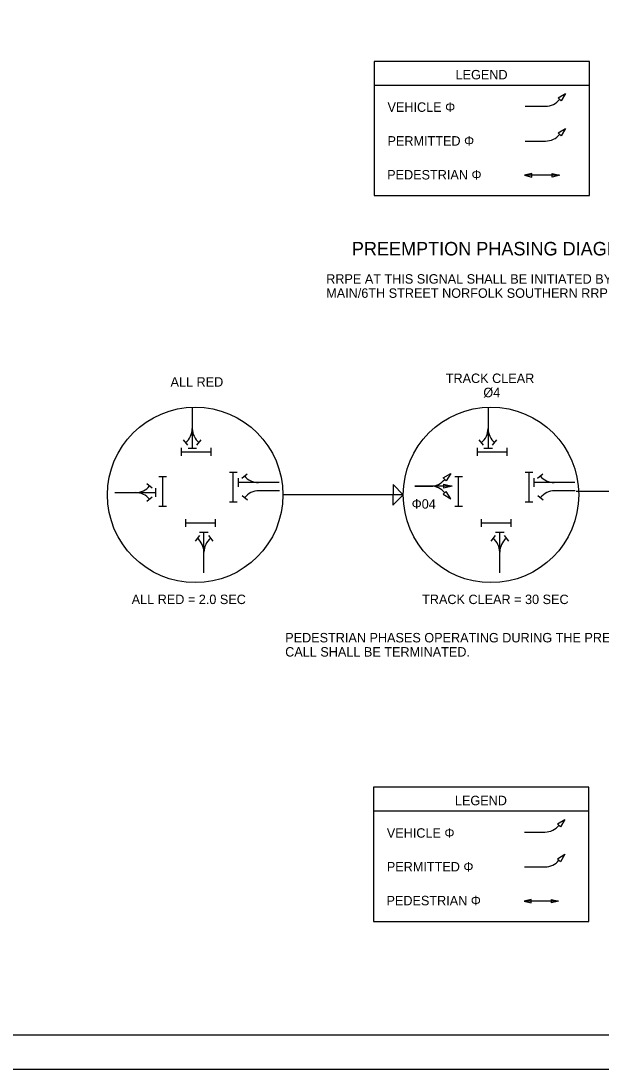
# Model space of a CAD drawing. Extents: x 0 to 680, y 0 to 551.
# Drawn here: x 337.3 to 509.1, y 0 to 310.4 of the extents above; entities that cross this region are included whole.
import ezdxf

# ---------------------------------------------------------------- set-up
doc = ezdxf.new("R2010")
doc.units = 0
for name, color, linetype in [('SG_P_Text', 7, 'Continuous'), ('SH_Border', 7, 'Continuous'), ('SH_Cut_Line', 7, 'Continuous'), ('SH_Data', 7, 'Continuous'), ('SH_Text', 7, 'Continuous')]:
    doc.layers.add(name, color=color, linetype=linetype)

msp = doc.modelspace()

# ---------------------------------------------------------------- linework, layer by layer
at = {"layer": 'SG_P_Text'}
for p, q in [((441.87, 291.42), (505.68, 291.42)), ((486.59, 285.15), (492.7, 285.15)), ((486.59, 274.82), (492.7, 274.82)), ((496.76, 264.68), (486.49, 264.68)), ((388.06, 195.78), (388.06, 189.67)), ((388.06, 195.78), (388.06, 189.67)), ((388.06, 195.78), (388.06, 183.77)), ((475.66, 195.78), (475.66, 189.67)), ((475.66, 195.78), (475.66, 189.67)), ((475.66, 195.78), (475.66, 183.77)), ((386.72, 184.74), (385.44, 186.33)), ((389.39, 184.74), (390.68, 186.33)), ((474.32, 184.74), (473.04, 186.33)), ((477, 184.74), (478.28, 186.33)), ((384.8, 183.93), (384.8, 181.65)), ((389.32, 183.77), (386.79, 183.77)), ((393.57, 183.93), (393.57, 181.65)), ((472.4, 183.93), (472.4, 181.65)), ((476.93, 183.77), (474.39, 183.77)), ((481.18, 183.93), (481.18, 181.65)), ((384.8, 182.79), (393.57, 182.79)), ((472.4, 182.79), (481.18, 182.79)), ((380.46, 175.42), (378.18, 175.42)), ((379.32, 166.64), (379.32, 175.42)), ((401.32, 176.65), (399.04, 176.65)), ((400.18, 167.88), (400.18, 176.65)), ((401.74, 172.42), (401.74, 174.95)), ((402.71, 175.03), (404.3, 176.31)), ((468.07, 175.42), (465.79, 175.42)), ((466.93, 166.64), (466.93, 175.42)), ((488.92, 176.65), (486.64, 176.65)), ((487.78, 167.88), (487.78, 176.65)), ((489.34, 172.42), (489.34, 174.95)), ((490.32, 175.03), (491.91, 176.31)), ((376.2, 172.05), (374.6, 173.33)), ((377.17, 171.98), (377.17, 169.44)), ((413.75, 173.69), (401.74, 173.69)), ((413.75, 173.69), (407.64, 173.69)), ((413.84, 171.23), (407.73, 171.23)), ((454.01, 172.63), (458.67, 172.63)), ((465.02, 172.63), (454.01, 172.63)), ((454.01, 172.63), (458.67, 172.63)), ((501.35, 173.69), (489.34, 173.69)), ((501.35, 173.69), (495.24, 173.69)), ((501.45, 171.23), (495.34, 171.23)), ((365.16, 170.71), (377.17, 170.71)), ((365.16, 170.71), (371.27, 170.71)), ((365.16, 170.71), (371.27, 170.71)), ((376.2, 169.37), (374.6, 168.09)), ((401.32, 167.88), (399.04, 167.88)), ((402.81, 169.89), (404.4, 168.61)), ((488.92, 167.88), (486.64, 167.88)), ((490.41, 169.89), (492, 168.61)), ((380.46, 166.64), (378.18, 166.64)), ((468.07, 166.64), (465.79, 166.64)), ((386.01, 162.86), (386.01, 160.58)), ((386.01, 161.72), (394.78, 161.72)), ((394.78, 162.86), (394.78, 160.58)), ((473.61, 162.86), (473.61, 160.58)), ((473.61, 161.72), (482.39, 161.72)), ((482.39, 162.86), (482.39, 160.58)), ((390.23, 158.95), (392.77, 158.95)), ((391.5, 146.94), (391.5, 158.95)), ((477.84, 158.95), (480.38, 158.95)), ((479.11, 146.94), (479.11, 158.95)), ((390.16, 157.98), (388.88, 156.38)), ((392.84, 157.98), (394.12, 156.38)), ((477.77, 157.98), (476.49, 156.38)), ((480.45, 157.98), (481.73, 156.38)), ((391.5, 146.94), (391.5, 153.05)), ((391.5, 146.94), (391.5, 153.05)), ((479.11, 146.94), (479.11, 153.05)), ((479.11, 146.94), (479.11, 153.05)), ((441.68, 76.46), (505.49, 76.46)), ((486.4, 70.19), (492.51, 70.19)), ((486.4, 59.85), (492.51, 59.85)), ((496.56, 49.71), (486.3, 49.71))]:
    msp.add_line(p, q, dxfattribs=at)
for points in [[(505.68, 298.42), (441.91, 298.42), (441.91, 258.67), (505.68, 258.67)], [(496.39, 287.58), (498.6, 288.9), (497.27, 286.69)], [(496.39, 277.24), (498.6, 278.56), (497.27, 276.35)], [(488.58, 265.2), (486.49, 264.68), (488.58, 264.16)], [(494.67, 265.2), (496.76, 264.68), (494.67, 264.16)], [(462.36, 175.05), (464.58, 176.37), (463.25, 174.16)], [(462.36, 170.21), (464.58, 168.88), (463.25, 171.09)], [(462.52, 173.25), (465.02, 172.63), (462.52, 172)], [(505.49, 83.46), (441.72, 83.46), (441.72, 43.71), (505.49, 43.71)], [(496.2, 72.61), (498.41, 73.94), (497.08, 71.73)], [(496.2, 62.27), (498.41, 63.6), (497.08, 61.39)], [(488.38, 50.23), (486.3, 49.71), (488.38, 49.19)], [(494.48, 50.23), (496.56, 49.71), (494.48, 49.19)]]:
    msp.add_lwpolyline(points, close=True, dxfattribs=at)
for centre in [(388.91, 170.04), (476.52, 170.04)]:
    msp.add_circle(centre, 25.99, dxfattribs=at)
for centre, start, end in [((492.7, 290.46), 270.0129, 321.2136), ((492.7, 280.12), 270, 321.2007), ((382.76, 189.67), 308.7993, 0), ((393.36, 189.67), 180, 231.2007), ((470.36, 189.67), 308.7993, 0), ((480.96, 189.67), 180, 231.2007), ((407.64, 178.99), 218.7864, 269.9871), ((458.67, 177.93), 270, 321.2007), ((495.24, 178.99), 218.7864, 269.9871), ((371.27, 176.01), 270, 321.2007), ((407.73, 165.93), 90.0129, 141.2136), ((458.67, 167.33), 38.7993, 90), ((495.34, 165.93), 90.0129, 141.2136), ((371.27, 165.41), 38.7993, 90), ((386.2, 153.05), 360, 51.2007), ((396.8, 153.05), 128.7993, 180), ((473.81, 153.05), 360, 51.2007), ((484.41, 153.05), 128.7993, 180), ((492.51, 75.49), 270.0129, 321.2136), ((492.51, 65.15), 270, 321.2007)]:
    msp.add_arc(centre, 5.3, start, end, dxfattribs=at)
at = {"layer": 'SH_Border'}
msp.add_lwpolyline([(30, 430), (670, 430), (670, 10), (30, 10)], close=True, dxfattribs=at)
at = {"layer": 'SH_Cut_Line'}
msp.add_lwpolyline([(0, 0), (680, 0), (680, 440), (0, 440)], close=True, dxfattribs=at)
at = {"layer": 'SH_Data'}
for p, q in [((537.42, 171.02), (501.79, 171.02)), ((450.53, 170.04), (414.91, 170.04))]:
    msp.add_line(p, q, dxfattribs=at)
msp.add_lwpolyline([(450.53, 170.04), (447.5, 173.07), (447.49, 167.01)], close=True, dxfattribs=at)

# ---------------------------------------------------------------- texts
at = {"layer": 'SG_P_Text'}
for s, p in [('LEGEND', (466.03, 293.09)), ('VEHICLE Φ', (445.87, 283.48)), ('PERMITTED Φ', (445.87, 273.48)), ('PEDESTRIAN Φ', (445.77, 263.45)), ('Φ04', (453.02, 165.96)), ('PEDESTRIAN PHASES OPERATING DURING THE PREEMPTION', (415.57, 126.35)), ('CALL SHALL BE TERMINATED.', (415.57, 122.15)), ('LEGEND', (465.84, 78.13)), ('VEHICLE Φ', (445.67, 68.51)), ('PERMITTED Φ', (445.67, 58.51)), ('PEDESTRIAN Φ', (445.57, 48.49))]:
    msp.add_text(s, height=2.8, dxfattribs=at).set_placement(p)
at = {"layer": 'SH_Text'}
for s, height, p in [('PREEMPTION PHASING DIAGRAM', 4, (435.31, 240.95)), ('RRPE AT THIS SIGNAL SHALL BE INITIATED BY INPUT FROM', 2.8, (427.71, 232.6)), ('MAIN/6TH STREET NORFOLK SOUTHERN RRPE PEDESTAL', 2.8, (427.71, 228.4)), ('ALL RED', 2.8, (381.61, 202.1)), ('TRACK CLEAR', 2.8, (463.12, 203.17)), ('Ø4', 2.8, (474.25, 198.97)), ('ALL RED = 2.0 SEC', 2.8, (370.1, 137.7)), ('TRACK CLEAR = 30 SEC', 2.8, (456.12, 137.7))]:
    msp.add_text(s, height=height, dxfattribs=at).set_placement(p)

doc.saveas('drawing.dxf')
